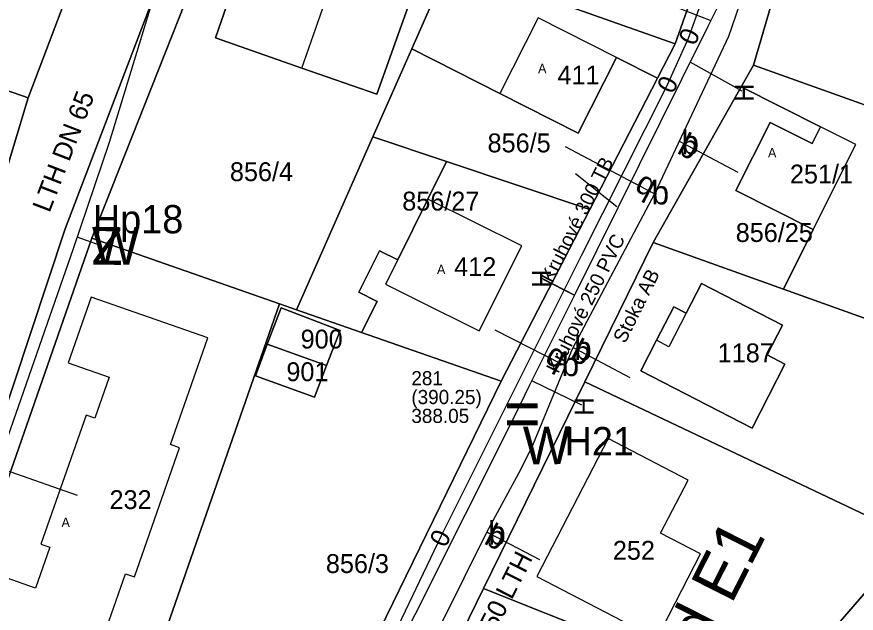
# Model space of a CAD drawing. Extents: x -564940 to -564406, y -1066466 to -1066072.
# Drawn here: x -564627.7 to -564538.7, y -1066287.6 to -1066224.4 of the extents above; entities that cross this region are included whole.
import ezdxf

# ---------------------------------------------------------------- set-up
doc = ezdxf.new("R2010")
doc.units = 0
for name, color, linetype in [('ft_g_5211', 7, 'Continuous'), ('ft_g_5411', 7, 'Continuous'), ('ft_g_5451', 7, 'Continuous'), ('ft_g_5451_ft_g_5451_da_5452_gtc_da_5452', 7, 'Continuous'), ('ft_g_6031', 7, 'Continuous'), ('ft_g_6040', 7, 'Continuous'), ('ft_g_6101', 7, 'Continuous'), ('ft_g_6101_ft_g_6101_da_6108_gtc_da_6108', 7, 'Continuous'), ('ft_g_6220', 7, 'Continuous'), ('ft_g_gps_hydrant', 7, 'Continuous'), ('ft_g_gps_soupe_pri', 7, 'Continuous'), ('ft_g_stoka', 7, 'Continuous'), ('ft_g_stoka_ft_g_stoka_da_oznaceni_gtc_da_6027', 7, 'Continuous'), ('ft_g_stoka_ft_g_stoka_da_popis_gtc_da_6004', 7, 'Continuous'), ('ft_g_vrad', 7, 'Continuous'), ('ft_g_vrad_ft_g_vrad_da_oznaceni_gtc_da_5095', 7, 'Continuous'), ('ft_g_vrad_ft_g_vrad_da_popis_gtc_da_5091', 7, 'Continuous'), ('ft_parcela_polygon', 7, 'Continuous'), ('ft_parcela_text', 7, 'Continuous'), ('ft_stavebni_objekt_bod', 7, 'Continuous'), ('ft_stavebni_objekt_polygon', 7, 'Continuous')]:
    doc.layers.add(name, color=color, linetype=linetype)

msp = doc.modelspace()

# ---------------------------------------------------------------- linework, layer by layer
at = {"layer": 'ft_g_5211'}
msp.add_line((-564629.871, -1066272.108), (-564621.334, -1066275.09), dxfattribs=at)
for points in [[(-564560.102, -1066243.143), (-564560.363, -1066243.005), (-564560.394, -1066242.988), (-564569.527, -1066238.158)], [(-564557.466, -1066237.545), (-564557.203, -1066237.685), (-564551.25, -1066240.841)], [(-564569.553, -1066261.389), (-564569.906, -1066261.208), (-564569.923, -1066261.199), (-564576.981, -1066257.58)], [(-564568.717, -1066259.428), (-564568.575, -1066259.503), (-564562.725, -1066262.61)], [(-564577.877, -1066278.989), (-564577.687, -1066279.088), (-564572.283, -1066281.897)]]:
    msp.add_lwpolyline(points, dxfattribs=at)
at = {"layer": 'ft_g_6040'}
for p, q in [((-564557.86, -1066223.32), (-564554.121, -1066224.755)), ((-564550.788, -1066232.267), (-564556.31, -1066229.163)), ((-564564.103, -1066244.522), (-564568.49, -1066241.012)), ((-564568.582, -1066253.87), (-564572.08, -1066252.09)), ((-564571.857, -1066252.203), (-564568.582, -1066253.87)), ((-564567.785, -1066265.541), (-564573.099, -1066262.964))]:
    msp.add_line(p, q, dxfattribs=at)
at = {"layer": 'ft_g_stoka'}
for points in [[(-564553.41, -1066163.16), (-564553.48, -1066166.31), (-564548.89, -1066191.56), (-564549.63, -1066201.367), (-564551.365, -1066210.526), (-564553.548, -1066218.367), (-564556.52, -1066226.67), (-564558.83, -1066231.76), (-564567.865, -1066249.71), (-564582.71, -1066279.41), (-564586.53, -1066287.4), (-564596.46, -1066308.15), (-564604.5, -1066323.01), (-564613.83, -1066341.28), (-564619.05, -1066351.65), (-564629.23, -1066370.83), (-564638.15, -1066388.86), (-564652.7, -1066417.07), (-564664.74, -1066439.37), (-564677.25, -1066462.42), (-564679.033, -1066465.633)], [(-564552.35, -1066221.19), (-564554.433, -1066225.385), (-564557.225, -1066231.006), (-564568.49, -1066253.685), (-564573.406, -1066263.582), (-564574.81, -1066266.41)], [(-564574.81, -1066266.41), (-564590.896, -1066298.495), (-564591.235, -1066299.172), (-564593.34, -1066303.37)]]:
    msp.add_lwpolyline(points, dxfattribs=at)
at = {"layer": 'ft_g_vrad'}
msp.add_line((-564618.768, -1066248.646), (-564621.335, -1066247.74), dxfattribs=at)
for points in [[(-564620.482, -1066101.725), (-564620.178, -1066103.951), (-564620.08, -1066104.481), (-564611.187, -1066150.389), (-564610.584, -1066152.835), (-564605.147, -1066183.365), (-564606.081, -1066198.866), (-564617.93, -1066237.697), (-564621.762, -1066248.96), (-564630.119, -1066272.816), (-564643.789, -1066306.495), (-564659.262, -1066341.651), (-564662.099, -1066345.128), (-564696.408, -1066409.187)], [(-564545.095, -1066199.879), (-564546.212, -1066208.866), (-564552.252, -1066226.474), (-564560.102, -1066243.143), (-564568.818, -1066259.619), (-564573.049, -1066269.82)], [(-564573.049, -1066269.82), (-564574.288, -1066272.325), (-564577.914, -1066279.058), (-564602.05, -1066327.684), (-564604.482, -1066332.963), (-564632.283, -1066386.015), (-564638.665, -1066398.966), (-564652.448, -1066423.533), (-564669.317, -1066454.463), (-564675.338, -1066465.633)]]:
    msp.add_lwpolyline(points, dxfattribs=at)
at = {"layer": 'ft_parcela_polygon'}
for points in [[(-564731.272, -1066465.633), (-564730.88, -1066465.02), (-564717.88, -1066445.03), (-564696.48, -1066409.93), (-564680.08, -1066379.48), (-564666.81, -1066354.64), (-564644.67, -1066309.69), (-564640.93, -1066302.01), (-564622.61, -1066246.86), (-564608.45, -1066209.76), (-564605.69, -1066192.25), (-564605.46, -1066182.07), (-564606.02, -1066175.01), (-564609.83, -1066156.99), (-564613.13, -1066141.3), (-564616.8, -1066123.25), (-564619.91, -1066107.51), (-564621.15, -1066099.64), (-564625.67, -1066074.88), (-564625.785, -1066072.016)], [(-564634.469, -1066072.016), (-564633.96, -1066075.48), (-564629.99, -1066098.11), (-564628.7, -1066106.04), (-564627.81, -1066111.53), (-564622.07, -1066142.43), (-564618.72, -1066163.1), (-564617.11, -1066172.99), (-564616.67, -1066175.71), (-564615.51, -1066182.89), (-564616.16, -1066192.04), (-564616.94, -1066202.99), (-564617.71, -1066205.75), (-564619.05, -1066210.58), (-564619.58, -1066212.49), (-564621.77, -1066220.35), (-564626.53, -1066232.96), (-564630.28, -1066245.31), (-564634.38, -1066256.8), (-564641.29, -1066276.14), (-564641.69, -1066277.26), (-564651.71, -1066302.17)], [(-564625.785, -1066072.016), (-564625.67, -1066074.88), (-564621.15, -1066099.64), (-564619.91, -1066107.51), (-564616.8, -1066123.25), (-564613.13, -1066141.3), (-564609.83, -1066156.99), (-564606.02, -1066175.01), (-564605.46, -1066182.07), (-564605.69, -1066192.25), (-564608.45, -1066209.76), (-564622.61, -1066246.86), (-564640.93, -1066302.01)], [(-564636.39, -1066295.43), (-564619.78, -1066247.85), (-564606.39, -1066213.99), (-564605.04, -1066210.59), (-564601.61, -1066192.31), (-564602.47, -1066181.82), (-564603.08, -1066174.43), (-564606.89, -1066156.37), (-564607.13, -1066155.22), (-564610.19, -1066140.68), (-564613.86, -1066122.67), (-564615.7, -1066113.36), (-564616.95, -1066107.05), (-564618.14, -1066099.45), (-564621.96, -1066074.15), (-564622.022, -1066072.016)], [(-564571.732, -1066072.016), (-564569.5, -1066088.72), (-564567.94, -1066097.08), (-564565.99, -1066106.59), (-564561.5, -1066130.67), (-564560.85, -1066134.21), (-564554.92, -1066165.61), (-564551.26, -1066180.91), (-564550.67, -1066194.76), (-564550.71, -1066199.59), (-564553.4, -1066214.51), (-564557.91, -1066227.24), (-564559.79, -1066230.88), (-564566.96, -1066244.79), (-564576.35, -1066263.01), (-564598.63, -1066308.62)], [(-564591.08, -1066311.25), (-564578.22, -1066284.98), (-564567.5, -1066263.08), (-564560.25, -1066248.28), (-564550.9, -1066231.8), (-564549.59, -1066229.5), (-564545.66, -1066216.05), (-564542.27, -1066200.44), (-564541.76, -1066192.23), (-564543.18, -1066178.64), (-564545.06, -1066168.72), (-564546.4, -1066162.66), (-564550.58, -1066143.31), (-564557.86, -1066106.36), (-564560.44, -1066091.42), (-564562.23, -1066080.42), (-564563.412, -1066072.016)]]:
    msp.add_lwpolyline(points, dxfattribs=at)
for points in [[(-564557.91, -1066227.24), (-564553.4, -1066214.51), (-564550.71, -1066199.59), (-564550.67, -1066194.76), (-564575.68, -1066193.56), (-564577.34, -1066201.66), (-564581.89, -1066218.77)], [(-564526.43, -1066237.76), (-564521.64, -1066222), (-564532.89, -1066219.22), (-564540.73, -1066217.33), (-564537.54, -1066205.54), (-564529.94, -1066207.38), (-564528.48, -1066201.53), (-564542.27, -1066200.44), (-564545.66, -1066216.05), (-564549.59, -1066229.5)], [(-564606.67, -1066226.6), (-564597.49, -1066229.8), (-564589.53, -1066232.57), (-564584.32, -1066217.92), (-564605.04, -1066210.59), (-564606.39, -1066213.99), (-564602.72, -1066215.27)], [(-564626.53, -1066232.96), (-564621.77, -1066220.35), (-564626.13, -1066219.18), (-564637.23, -1066216.19), (-564652.14, -1066212.82), (-564652.65, -1066219.21), (-564653.29, -1066224.17), (-564655.91, -1066234.9), (-564657.93, -1066242.66), (-564658.94, -1066246.54), (-564660.74, -1066253.42), (-564642.13, -1066259.62), (-564634.38, -1066256.8), (-564630.28, -1066245.31), (-564633.4, -1066244.23), (-564637.69, -1066256.61), (-564644.54, -1066254.23), (-564645.36, -1066256.6), (-564647.96, -1066255.7), (-564647.14, -1066253.33), (-564653.99, -1066250.96), (-564649.69, -1066238.58), (-564645.47, -1066226.39), (-564639.85, -1066228.34)], [(-564581.89, -1066218.77), (-564584.32, -1066217.92), (-564589.53, -1066232.57), (-564597.49, -1066229.8), (-564606.67, -1066226.6), (-564602.72, -1066215.27), (-564606.39, -1066213.99), (-564619.78, -1066247.85), (-564599.86, -1066254.8), (-564598.07, -1066255.43), (-564589.97, -1066237.09), (-564585.85, -1066227.75)], [(-564576.5, -1066232.49), (-564568.2, -1066236.7), (-564564.13, -1066228.68), (-564559.79, -1066230.88), (-564557.91, -1066227.24), (-564581.89, -1066218.77), (-564585.85, -1066227.75)], [(-564626.53, -1066232.96), (-564639.85, -1066228.34), (-564645.47, -1066226.39), (-564649.69, -1066238.58), (-564653.99, -1066250.96), (-564647.14, -1066253.33), (-564647.96, -1066255.7), (-564645.36, -1066256.6), (-564644.54, -1066254.23), (-564637.69, -1066256.61), (-564633.4, -1066244.23), (-564630.28, -1066245.31)], [(-564582.14, -1066239.71), (-564566.96, -1066244.79), (-564559.79, -1066230.88), (-564564.13, -1066228.68), (-564568.2, -1066236.7), (-564576.5, -1066232.49), (-564585.85, -1066227.75), (-564589.97, -1066237.09)], [(-564534.18, -1066257.61), (-564529.74, -1066248.03), (-564533.91, -1066246.09), (-564529.59, -1066236.76), (-564526.56, -1066238.18), (-564526.43, -1066237.76), (-564549.59, -1066229.5), (-564550.9, -1066231.8), (-564542.48, -1066236.02), (-564543.37, -1066237.81), (-564547.84, -1066235.56), (-564551.47, -1066242.8), (-564543.25, -1066246.92), (-564546.41, -1066253.23)], [(-564547.84, -1066235.56), (-564543.37, -1066237.81), (-564542.48, -1066236.02), (-564550.9, -1066231.8), (-564560.25, -1066248.28), (-564546.41, -1066253.23), (-564543.25, -1066246.92), (-564551.47, -1066242.8)], [(-564598.07, -1066255.43), (-564591.16, -1066257.84), (-564589.52, -1066254.54), (-564591.47, -1066253.57), (-564589.28, -1066249.17), (-564587.33, -1066250.14), (-564584.12, -1066243.69), (-564582.14, -1066239.71), (-564589.97, -1066237.09)], [(-564591.16, -1066257.84), (-564576.35, -1066263.01), (-564566.96, -1066244.79), (-564582.14, -1066239.71), (-564584.12, -1066243.69), (-564587.33, -1066250.14), (-564589.28, -1066249.17), (-564591.47, -1066253.57), (-564589.52, -1066254.54)], [(-564599.86, -1066254.8), (-564619.78, -1066247.85), (-564636.39, -1066295.43), (-564616.47, -1066302.39)], [(-564560.25, -1066248.28), (-564567.5, -1066263.08), (-564532.7, -1066279.57), (-564518.53, -1066263.21), (-564534.18, -1066257.61), (-564546.41, -1066253.23)], [(-564558.06, -1066255.11), (-564556.74, -1066255.79), (-564555.11, -1066252.64), (-564546.52, -1066257.06), (-564548.14, -1066260.22), (-564546.26, -1066261.18), (-564549.75, -1066267.98), (-564561.55, -1066261.92), (-564559.87, -1066258.66)], [(-564558.06, -1066255.11), (-564559.87, -1066258.66), (-564561.55, -1066261.92), (-564549.75, -1066267.98), (-564546.26, -1066261.18), (-564548.14, -1066260.22), (-564546.52, -1066257.06), (-564555.11, -1066252.64), (-564556.74, -1066255.79)], [(-564576.35, -1066263.01), (-564591.16, -1066257.84), (-564598.07, -1066255.43), (-564599.86, -1066254.8), (-564616.47, -1066302.39), (-564598.63, -1066308.62)], [(-564601.18, -1066259.08), (-564599.69, -1066255.21), (-564593.43, -1066257.62), (-564594.87, -1066261.35), (-564596.16, -1066264.71), (-564602.4, -1066262.42)], [(-564601.18, -1066259.08), (-564594.87, -1066261.35), (-564593.43, -1066257.62), (-564599.69, -1066255.21)], [(-564594.87, -1066261.35), (-564601.18, -1066259.08), (-564602.4, -1066262.42), (-564596.16, -1066264.71)], [(-564532.7, -1066279.57), (-564567.5, -1066263.08), (-564578.22, -1066284.98), (-564558.28, -1066292.94), (-564547.86, -1066297.09)], [(-564534.97, -1066302.23), (-564526.09, -1066292.91), (-564519.39, -1066285.88), (-564532.7, -1066279.57), (-564547.86, -1066297.09)], [(-564574.82, -1066292.32), (-564568.22, -1066295.67), (-564566.97, -1066296.31), (-564564.62, -1066291.86), (-564559.2, -1066294.72), (-564558.28, -1066292.94), (-564578.22, -1066284.98), (-564591.08, -1066311.25), (-564584.02, -1066313.73), (-564572.57, -1066304.16), (-564580.83, -1066299.88), (-564576.48, -1066291.48)]]:
    msp.add_lwpolyline(points, close=True, dxfattribs=at)
at = {"layer": 'ft_stavebni_objekt_polygon'}
for points in [[(-564602.72, -1066215.27), (-564606.67, -1066226.6), (-564597.49, -1066229.8), (-564593.54, -1066218.47)], [(-564576.5, -1066232.49), (-564568.2, -1066236.7), (-564564.13, -1066228.68), (-564572.42, -1066224.47)], [(-564547.84, -1066235.56), (-564551.47, -1066242.8), (-564543.25, -1066246.92), (-564538.72, -1066237.9), (-564542.48, -1066236.02), (-564543.37, -1066237.81)], [(-564588.63, -1066252.73), (-564585.45, -1066254.29), (-564578.69, -1066257.68), (-564574.18, -1066248.64), (-564584.12, -1066243.69), (-564587.33, -1066250.14)], [(-564559.87, -1066258.66), (-564561.55, -1066261.92), (-564549.75, -1066267.98), (-564546.26, -1066261.18), (-564548.14, -1066260.22), (-564546.52, -1066257.06), (-564555.11, -1066252.64), (-564556.74, -1066255.79), (-564558.56, -1066259.35)], [(-564632.53, -1066290.43), (-564620.16, -1066294.74), (-564616.2, -1066283.41), (-564615.26, -1066283.74), (-564610.48, -1066270.05), (-564611.43, -1066269.72), (-564607.47, -1066258.4), (-564619.84, -1066254.08), (-564622.28, -1066261.06), (-564617.93, -1066262.58), (-564619.45, -1066266.92), (-564620.39, -1066266.59), (-564625.17, -1066280.28), (-564624.23, -1066280.61), (-564625.75, -1066284.96), (-564630.09, -1066283.44)], [(-564572.59, -1066283.7), (-564559.85, -1066290.3), (-564555.2, -1066281.32), (-564559.44, -1066279.13), (-564556.54, -1066273.49), (-564565.02, -1066269.09)]]:
    msp.add_lwpolyline(points, close=True, dxfattribs=at)

# ---------------------------------------------------------------- texts
at = {"layer": 'ft_g_5411'}
for rotation, p in [(332.0706, (-564557.823, -1066238.771)), (152.12701, (-564559.775, -1066241.902)), (332.0269, (-564569.196, -1066260.589)), (152.84851, (-564569.317, -1066260.105)), (332.53284, (-564578.298, -1066280.179))]:
    msp.add_text('b', height=2.5, rotation=rotation, dxfattribs=at).set_placement(p)
at = {"layer": 'ft_g_5451'}
for s, rotation, p in [('Z', 359.20955, (-564619.795, -1066250.632)), ('W', 0.47625, (-564574.033, -1066271.829))]:
    msp.add_text(s, height=4, rotation=rotation, dxfattribs=at).set_placement(p)
at = {"layer": 'ft_g_5451_ft_g_5451_da_5452_gtc_da_5452'}
for s, p in [('Hp18', (-564619.668, -1066247.324)), ('H21', (-564569.633, -1066270.859))]:
    msp.add_text(s, height=3, dxfattribs=at).set_placement(p)
at = {"layer": 'ft_g_6031'}
for rotation, p in [(245.67147, (-564557.028, -1066225.352)), (243.28195, (-564559.276, -1066230.417)), (63.44264, (-564582.258, -1066280.745))]:
    msp.add_text('0', height=2, rotation=rotation, dxfattribs=at).set_placement(p)
at = {"layer": 'ft_g_6101'}
msp.add_text('=', height=5, dxfattribs=at).set_placement((-564576.06, -1066268.91))
at = {"layer": 'ft_g_6101_ft_g_6101_da_6108_gtc_da_6108'}
for s, p in [('281', (-564585.885, -1066263.43)), ('(390.25)', (-564585.885, -1066265.43)), ('388.05', (-564585.885, -1066267.43))]:
    msp.add_text(s, height=1.5, dxfattribs=at).set_placement(p)
at = {"layer": 'ft_g_6220'}
for p in [(-564549.57, -1066233.39), (-564571.08, -1066253.09), (-564566.56, -1066266.65)]:
    msp.add_text('H', height=2, rotation=89.99998, dxfattribs=at).set_placement(p)
at = {"layer": 'ft_g_gps_hydrant'}
msp.add_text('W', height=4, dxfattribs=at).set_placement((-564619.768, -1066250.646))
at = {"layer": 'ft_g_gps_soupe_pri'}
for p in [(-564557.242, -1066238.935), (-564560.402, -1066244.255), (-564568.614, -1066260.753), (-564569.945, -1066262.458), (-564577.726, -1066280.338)]:
    msp.add_text('b', height=2.5, dxfattribs=at).set_placement(p)
at = {"layer": 'ft_g_stoka_ft_g_stoka_da_oznaceni_gtc_da_6027'}
msp.add_text('Stoka AB', height=1.5, rotation=63.58571, dxfattribs=at).set_placement((-564563.216, -1066259.092))
at = {"layer": 'ft_g_stoka_ft_g_stoka_da_popis_gtc_da_6004'}
for s, rotation, p in [('Kruhové 300 TB', 63.28193, (-564570.905, -1066252.676)), ('Kruhové 250 PVC', 63.58571, (-564570.309, -1066262.265))]:
    msp.add_text(s, height=1.5, rotation=rotation, dxfattribs=at).set_placement(p)
at = {"layer": 'ft_g_vrad_ft_g_vrad_da_oznaceni_gtc_da_5095'}
msp.add_text('Řad E1', height=5, rotation=63.18556, dxfattribs=at).set_placement((-564558.303, -1066299.346))
at = {"layer": 'ft_g_vrad_ft_g_vrad_da_popis_gtc_da_5091'}
for s, rotation, p in [('LTH DN 65', 68.94327, (-564624.271, -1066245.224)), ('DN 150 LTH', 63.18556, (-564579.664, -1066295.004))]:
    msp.add_text(s, height=2, rotation=rotation, dxfattribs=at).set_placement(p)
at = {"layer": 'ft_parcela_text'}
for s, p in [('411', (-564570.38, -1066231.54)), ('856/5', (-564577.8, -1066238.74)), ('856/4', (-564605.13, -1066241.79)), ('251/1', (-564545.73, -1066242.04)), ('856/27', (-564586.85, -1066244.91)), ('856/25', (-564551.48, -1066248.24)), ('412', (-564581.34, -1066251.86)), ('900', (-564597.63, -1066259.54)), ('1187', (-564553.39, -1066261)), ('901', (-564599.14, -1066263)), ('232', (-564617.9, -1066276.56)), ('252', (-564564.51, -1066281.93)), ('856/3', (-564594.95, -1066283.34))]:
    msp.add_text(s, height=2, dxfattribs=at).set_placement(p)
at = {"layer": 'ft_stavebni_objekt_bod'}
for p in [(-564572.447, -1066230.35), (-564548.057, -1066239.28), (-564583.167, -1066251.65), (-564622.997, -1066278.47)]:
    msp.add_text('A', height=1, dxfattribs=at).set_placement(p)

doc.saveas('drawing.dxf')
